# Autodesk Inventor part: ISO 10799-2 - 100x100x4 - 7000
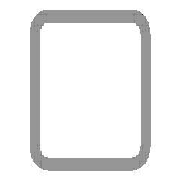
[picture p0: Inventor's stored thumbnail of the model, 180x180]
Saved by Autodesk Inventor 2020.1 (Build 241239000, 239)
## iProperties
Created: 2019-10
Part Number: ISO 10799-2 - 100x100x4 - 7000
Material: Stainless Steel
Description: Structural steels - Cold-formed, welded, structural hollow sections
Document SubType Name: Modeling
Standard: ISO
Designer: Synergysoft Dell02
Standard Revision: First edition 2011-09-15
Standards Organization: ISO
Language: en-US
Size Designation: 100x100x4
Categories: <MemberInstance><Categories><Category DisplayName="Structural Shapes" InternalName="089c4875-fa83-4c05-b084-43b9cc11f5ed" Mnemonic="GRDR"><CategoryParameter Dis
Stock Number: 100x100x4
Density: 8 g/cm^3
Appearance: Semi-Polished
_CCFamilyMember: 43
_CCFamilyDisplayName: ISO 10799-2 (Square) - Structural steels - Cold-formed, welded, structural hollow sections
_FrameMemberDoc: Frame Member File
_Version: 15.0.0
_GetPNFromCC: 1
G_L: 7000.000 mm
G_W: 100.000 mm
G_H: 100.000 mm
IsCustomPart: 1
Author: Synergysoft Dell02
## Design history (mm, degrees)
node "Start Plane"
node "End Plane"
sketch "Sketch"
  geometry: L1 (-50, -42)-(-50, 42); L2 (-42, 50)-(42, 50); L3 (50, 42)-(50, -42); L4 (42, -50)-(-42, -50); L5 (-42, 46)-(42, 46); L6 (46, 42)-(46, -42); L7 (42, -46)-(-42, -46); L8 (-46, -42)-(-46, 42); L9 (0, 72.32)-(0, -72.32) reference; L10 (-72.32, 0)-(72.32, 0) reference; A1 r 8 centre (-42, -42) between (-50, -42) and (-42, -50); A2 r 8 centre (42, 42) between (50, 42) and (42, 50); A3 r 8 centre (-42, 42) between (-42, 50) and (-50, 42); A4 r 8 centre (42, -42) between (42, -50) and (50, -42); A5 r 4 centre (-42, 42) between (-42, 46) and (-46, 42); A6 r 4 centre (42, 42) between (46, 42) and (42, 46); A7 r 4 centre (42, -42) between (42, -46) and (46, -42); A8 r 4 centre (-42, -42) between (-46, -42) and (-42, -46)
  constraints: 16 end point, 16 point on circle, 8 centre point, 8 tangent, 4 parallel, 3 equal radius, 2 perpendicular, 7 other
  dimensions: "d7" = 8 radius of A1 (= G_IR); "d9" = 100 distance between parallel lines of L1 L3 (= G_W); "d11" = 100 distance between parallel lines of L2 L4 (= G_H); "d12" = 4 distance between parallel lines of L3 L6 (= G_T); "d15" = 50 distance between parallel lines of L9 L3 (= 0.5 x d9); "d16" = 50 distance between parallel lines of L2 L10 (= 0.5 x d11)
extrude "Body" new body sketch "Sketch" stored distance "d3" = 7000 (= G_L); taper "d4" = 0 deg
node "Driven Length"
  sketch "Sketch3"
    geometry: L1 (0, 0)-(10, 0) reference
    constraints: 2 end point, 1 horizontal
  workplane "Work Plane3"
  sketch "Sketch4"
    geometry: L1 (-2, 0)-(12, 0) reference; L2 (-2, 7000)-(12, 7000) reference
    dimensions: "d18" = 7000 distance between parallel lines of L1 L2 (derived)
body "Solid1"
other parameters: "G_W" = 100 [user parameter; used in 1 equation term], "G_H" = 100 [user parameter; used in 1 equation term], "G_T" = 4 [user parameter; used in 1 equation term], "G_IR" = 8 [user parameter; used in 1 equation term], "G_L" = 7000 (= d18) [user parameter; used in 1 equation term], "G_OFFSET_START" = 0 [user parameter; used in 1 equation term], "G_OFFSET_END" = 0 [user parameter; used in 1 equation term], "d13" = 0 (computed from G_OFFSET_START), "d17" = 90 deg, "MAS" = 1.17 [user parameter]
